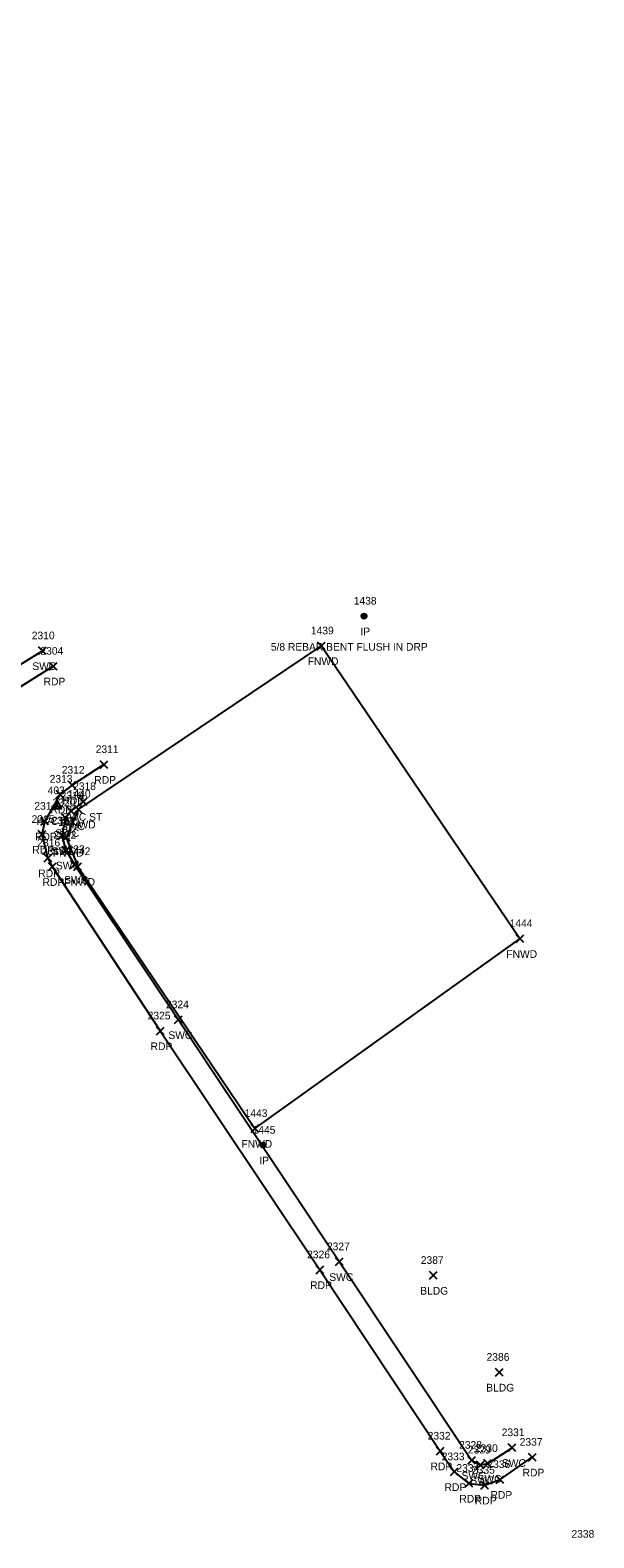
# Model space of a CAD drawing. Extents: x 1635588 to 1637550, y 621583 to 623638.
# Drawn here: x 1637037.4 to 1637184.3, y 622079.8 to 622472.5 of the extents above; entities that cross this region are included whole.
import ezdxf

# ---------------------------------------------------------------- set-up
doc = ezdxf.new("R2010")
doc.units = 0
for name, color, linetype in [('C_A', 7, 'Continuous'), ('C_I', 7, 'Continuous'), ('CPSM', 7, 'Continuous'), ('L_A', 7, 'Continuous'), ('L_I', 7, 'Continuous'), ('L_TIC', 7, 'Continuous'), ('LFNC', 7, 'Continuous'), ('M_A', 7, 'Continuous'), ('M_C', 7, 'Continuous'), ('M_I', 7, 'Continuous'), ('MPIR', 7, 'Continuous'), ('P_A', 7, 'Continuous'), ('P_I', 7, 'Continuous'), ('P_TIC', 7, 'Continuous'), ('PET', 7, 'Continuous'), ('R_A', 7, 'Continuous'), ('R_I', 7, 'Continuous'), ('R_TIC', 7, 'Continuous'), ('RSW', 7, 'Continuous')]:
    doc.layers.add(name, color=color, linetype=linetype)

msp = doc.modelspace()

# ---------------------------------------------------------------- linework, layer by layer
at = {"layer": 'CPSM'}
for p, q in [((1637043.15, 622269.75), (1637044.4, 622271.92)), ((1637045.65, 622269.75), (1637044.4, 622271.92)), ((1637044.4, 622270.47), (1637044.4, 622271.92)), ((1637043.15, 622269.75), (1637044.4, 622270.47)), ((1637043.15, 622269.75), (1637045.65, 622269.75)), ((1637044.4, 622270.47), (1637044.4, 622270.47)), ((1637044.4, 622270.47), (1637045.65, 622269.75))]:
    msp.add_line(p, q, dxfattribs=at)
at = {"layer": 'L_TIC'}
for points in [[(1637112.25, 622311.1), (1637114.25, 622313.1)], [(1637114.25, 622311.1), (1637112.25, 622313.1)], [(1637048.98, 622268.57), (1637050.98, 622270.57)], [(1637050.98, 622268.57), (1637048.98, 622270.57)], [(1637045.82, 622261.2), (1637047.82, 622263.2)], [(1637047.82, 622261.2), (1637045.82, 622263.2)], [(1637048.82, 622253.61), (1637050.82, 622255.61)], [(1637050.82, 622253.61), (1637048.82, 622255.61)], [(1637164.01, 622234.84), (1637166.01, 622236.84)], [(1637166.01, 622234.84), (1637164.01, 622236.84)], [(1637094.98, 622185.4), (1637096.98, 622187.4)], [(1637096.98, 622185.4), (1637094.98, 622187.4)], [(1637141.45, 622147.13), (1637143.45, 622149.13)], [(1637143.45, 622147.13), (1637141.45, 622149.13)], [(1637158.64, 622121.9), (1637160.64, 622123.9)], [(1637160.64, 622121.9), (1637158.64, 622123.9)]]:
    msp.add_lwpolyline(points, dxfattribs=at)
at = {"layer": 'LFNC'}
msp.add_lwpolyline([(1637113.25, 622312.1), (1637049.98, 622269.57), (1637046.82, 622262.2), (1637049.82, 622254.61), (1637095.98, 622186.4), (1637165.01, 622235.84), (1637113.25, 622312.1)], dxfattribs=at)
at = {"layer": 'MPIR'}
for points in [[(1637124.4, 622320.18), (1637124.12, 622319.68), (1637124.69, 622319.68)], [(1637098.05, 622182.4), (1637097.77, 622181.9), (1637098.34, 622181.9)]]:
    msp.add_lwpolyline(points, close=True, dxfattribs=at)
for centre in [(1637124.4, 622319.85), (1637098.05, 622182.06)]:
    msp.add_circle(centre, 0.667, dxfattribs=at)
at = {"layer": 'P_TIC'}
for points in [[(1637042.41, 622305.81), (1637044.41, 622307.81)], [(1637044.41, 622305.81), (1637042.41, 622307.81)], [(1637055.62, 622280.2), (1637057.62, 622282.2)], [(1637057.62, 622280.2), (1637055.62, 622282.2)], [(1637047.33, 622274.83), (1637049.33, 622276.83)], [(1637049.33, 622274.83), (1637047.33, 622276.83)], [(1637044.18, 622272.47), (1637046.18, 622274.47)], [(1637046.18, 622272.47), (1637044.18, 622274.47)], [(1637040.19, 622265.43), (1637042.19, 622267.43)], [(1637042.19, 622265.43), (1637040.19, 622267.43)], [(1637039.47, 622261.99), (1637041.47, 622263.99)], [(1637041.47, 622261.99), (1637039.47, 622263.99)], [(1637041.02, 622255.85), (1637043.02, 622257.85)], [(1637043.02, 622255.85), (1637041.02, 622257.85)], [(1637042.15, 622253.6), (1637044.15, 622255.6)], [(1637044.15, 622253.6), (1637042.15, 622255.6)], [(1637070.29, 622210.81), (1637072.29, 622212.81)], [(1637072.29, 622210.81), (1637070.29, 622212.81)], [(1637111.88, 622148.59), (1637113.88, 622150.59)], [(1637113.88, 622148.59), (1637111.88, 622150.59)], [(1637143.24, 622101.38), (1637145.24, 622103.38)], [(1637145.24, 622101.38), (1637143.24, 622103.38)], [(1637167.22, 622099.78), (1637169.22, 622101.78)], [(1637169.22, 622099.78), (1637167.22, 622101.78)], [(1637146.89, 622095.99), (1637148.89, 622097.99)], [(1637148.89, 622095.99), (1637146.89, 622097.99)], [(1637150.73, 622092.98), (1637152.73, 622094.98)], [(1637152.73, 622092.98), (1637150.73, 622094.98)], [(1637158.86, 622093.97), (1637160.86, 622095.97)], [(1637160.86, 622093.97), (1637158.86, 622095.97)], [(1637154.79, 622092.49), (1637156.79, 622094.49)], [(1637156.79, 622092.49), (1637154.79, 622094.49)]]:
    msp.add_lwpolyline(points, dxfattribs=at)
at = {"layer": 'PET'}
for points in [[(1636911.05, 622472.47), (1636908.81, 622467.93), (1636907.57, 622463.09), (1636908.26, 622457.7), (1636909.83, 622453.84), (1636922.75, 622434.77), (1636956.87, 622383.45), (1637005.57, 622310.7), (1637012.54, 622300.22), (1637018.89, 622297.29), (1637022.03, 622296.63), (1637025.42, 622297.04), (1637030.28, 622298.66), (1637033.43, 622300.54), (1637043.41, 622306.81)], [(1637056.62, 622281.2), (1637048.33, 622275.83), (1637045.18, 622273.47), (1637041.19, 622266.43), (1637040.47, 622262.99), (1637042.02, 622256.85), (1637043.15, 622254.6), (1637071.29, 622211.81), (1637112.88, 622149.59), (1637144.24, 622102.38), (1637147.89, 622096.99), (1637151.73, 622093.98), (1637155.79, 622093.49), (1637159.86, 622094.97), (1637168.22, 622100.78)]]:
    msp.add_lwpolyline(points, dxfattribs=at)
at = {"layer": 'R_TIC'}
for points in [[(1637039.61, 622309.82), (1637041.61, 622311.82)], [(1637041.61, 622309.82), (1637039.61, 622311.82)], [(1637050.29, 622270.56), (1637052.29, 622272.56)], [(1637052.29, 622270.56), (1637050.29, 622272.56)], [(1637045.57, 622266.34), (1637047.57, 622268.34)], [(1637047.57, 622266.34), (1637045.57, 622268.34)], [(1637047.05, 622268.12), (1637049.05, 622270.12)], [(1637049.05, 622268.12), (1637047.05, 622270.12)], [(1637044.68, 622261.63), (1637046.68, 622263.63)], [(1637046.68, 622261.63), (1637044.68, 622263.63)], [(1637045.73, 622257.89), (1637047.73, 622259.89)], [(1637047.73, 622257.89), (1637045.73, 622259.89)], [(1637047.92, 622254.15), (1637049.92, 622256.15)], [(1637049.92, 622254.15), (1637047.92, 622256.15)], [(1637075.05, 622213.72), (1637077.05, 622215.72)], [(1637077.05, 622213.72), (1637075.05, 622215.72)], [(1637116.99, 622150.7), (1637118.99, 622152.7)], [(1637118.99, 622150.7), (1637116.99, 622152.7)], [(1637161.96, 622102.27), (1637163.96, 622104.27)], [(1637163.96, 622102.27), (1637161.96, 622104.27)], [(1637151.43, 622098.99), (1637153.43, 622100.99)], [(1637153.43, 622098.99), (1637151.43, 622100.99)], [(1637153.73, 622097.76), (1637155.73, 622099.76)], [(1637155.73, 622097.76), (1637153.73, 622099.76)], [(1637155.63, 622098.15), (1637157.63, 622100.15)], [(1637157.63, 622098.15), (1637155.63, 622100.15)]]:
    msp.add_lwpolyline(points, dxfattribs=at)
at = {"layer": 'RSW'}
for points in [[(1636914.59, 622467.64), (1636913.06, 622462.83), (1636913.39, 622459.51), (1636914.78, 622456.61), (1636917.39, 622452.3), (1636927.33, 622437.77), (1636961.45, 622386.53), (1637010.15, 622313.71), (1637016.86, 622304.02), (1637019.49, 622302.28), (1637022.85, 622301.89), (1637026.51, 622302.69), (1637029.44, 622303.95), (1637040.61, 622310.82)], [(1637051.29, 622271.56), (1637048.05, 622269.12), (1637046.57, 622267.34), (1637045.68, 622262.63), (1637046.73, 622258.89), (1637048.92, 622255.15), (1637076.05, 622214.72), (1637117.99, 622151.7), (1637152.43, 622099.99), (1637154.73, 622098.76), (1637156.63, 622099.15), (1637162.96, 622103.27)]]:
    msp.add_lwpolyline(points, dxfattribs=at)

# ---------------------------------------------------------------- texts
at = {"layer": 'C_A'}
msp.add_text('HVCTRL', height=2, dxfattribs=at).set_placement((1637039.09, 622265.47))
at = {"layer": 'C_I'}
msp.add_text('403', height=2, dxfattribs=at).set_placement((1637041.96, 622273.47))
at = {"layer": 'L_A'}
for s, p in [('FNWD', (1637109.72, 622307.1)), ('FNWD', (1637046.44, 622264.57)), ('FNWD', (1637043.29, 622257.2)), ('FNWD', (1637046.28, 622249.61)), ('FNWD', (1637161.47, 622230.84)), ('FNWD', (1637092.44, 622181.4)), ('BLDG', (1637139.04, 622143.13)), ('BLDG', (1637156.23, 622117.9))]:
    msp.add_text(s, height=2, dxfattribs=at).set_placement(p)
at = {"layer": 'L_I'}
for s, p in [('1439', (1637110.55, 622315.1)), ('1440', (1637047.2, 622272.57)), ('1441', (1637044.7, 622265.2)), ('1442', (1637047.13, 622257.61)), ('1444', (1637162.32, 622238.84)), ('1443', (1637093.28, 622189.4)), ('2387', (1637139.19, 622151.13)), ('2386', (1637156.32, 622125.9))]:
    msp.add_text(s, height=2, dxfattribs=at).set_placement(p)
at = {"layer": 'M_A'}
for p in [(1637123.45, 622314.85), (1637097.1, 622177.06)]:
    msp.add_text('IP', height=2, dxfattribs=at).set_placement(p)
at = {"layer": 'M_C'}
msp.add_text('5/8 REBAR BENT FLUSH IN DRP', height=2, dxfattribs=at).set_placement((1637100.11, 622310.85))
at = {"layer": 'M_I'}
for s, p in [('1438', (1637121.71, 622322.85)), ('1445', (1637095.36, 622185.06))]:
    msp.add_text(s, height=2, dxfattribs=at).set_placement(p)
at = {"layer": 'P_A'}
for p in [(1637040.9, 622301.81), (1637054.11, 622276.2), (1637045.82, 622270.83), (1637042.67, 622268.47), (1637037.96, 622257.99), (1637038.68, 622261.43), (1637039.51, 622251.85), (1637040.63, 622249.6), (1637068.78, 622206.81), (1637110.37, 622144.59), (1637141.72, 622097.38), (1637165.71, 622095.78), (1637145.38, 622091.99), (1637149.22, 622088.98), (1637157.35, 622089.97), (1637153.28, 622088.49)]:
    msp.add_text('RDP', height=2, dxfattribs=at).set_placement(p)
at = {"layer": 'P_I'}
for s, p in [('2304', (1637040.07, 622309.81)), ('2311', (1637054.49, 622284.2)), ('2312', (1637045.64, 622278.83)), ('2313', (1637042.48, 622276.47)), ('2314', (1637038.5, 622269.43)), ('2315', (1637037.78, 622265.99)), ('2316', (1637039.28, 622259.85)), ('2317', (1637040.45, 622257.6)), ('2325', (1637068.03, 622214.81)), ('2326', (1637109.57, 622152.59)), ('2332', (1637140.98, 622105.38)), ('2337', (1637164.96, 622103.78)), ('2333', (1637144.63, 622099.99)), ('2334', (1637148.47, 622096.98)), ('2335', (1637152.53, 622096.49)), ('2336', (1637156.54, 622097.97)), ('2338', (1637178.44, 622079.82))]:
    msp.add_text(s, height=2, dxfattribs=at).set_placement(p)
at = {"layer": 'R_A'}
for s, p in [('SWC', (1637037.97, 622305.82)), ('SWC ST', (1637045.78, 622266.56)), ('SWC', (1637043.94, 622262.34)), ('SWC', (1637045.42, 622264.12)), ('SWC', (1637043.04, 622257.63)), ('SWC', (1637044.1, 622253.89)), ('SWC', (1637046.28, 622250.15)), ('SWC', (1637073.41, 622209.72)), ('SWC', (1637115.35, 622146.7)), ('SWC', (1637160.33, 622098.27)), ('SWC', (1637149.79, 622094.99)), ('SWC', (1637152.09, 622093.76)), ('SWC', (1637153.99, 622094.15))]:
    msp.add_text(s, height=2, dxfattribs=at).set_placement(p)
at = {"layer": 'R_I'}
for s, p in [('2310', (1637037.83, 622313.82)), ('2318', (1637048.59, 622274.56)), ('2320', (1637043.23, 622270.34)), ('2319', (1637045.35, 622272.12)), ('2321', (1637042.99, 622265.63)), ('2322', (1637043.47, 622261.89)), ('2323', (1637045.66, 622258.15)), ('2324', (1637072.79, 622217.72)), ('2327', (1637114.73, 622154.7)), ('2331', (1637160.27, 622106.27)), ('2328', (1637149.17, 622102.99)), ('2329', (1637151.46, 622101.76)), ('2330', (1637153.28, 622102.15))]:
    msp.add_text(s, height=2, dxfattribs=at).set_placement(p)

doc.saveas('drawing.dxf')
